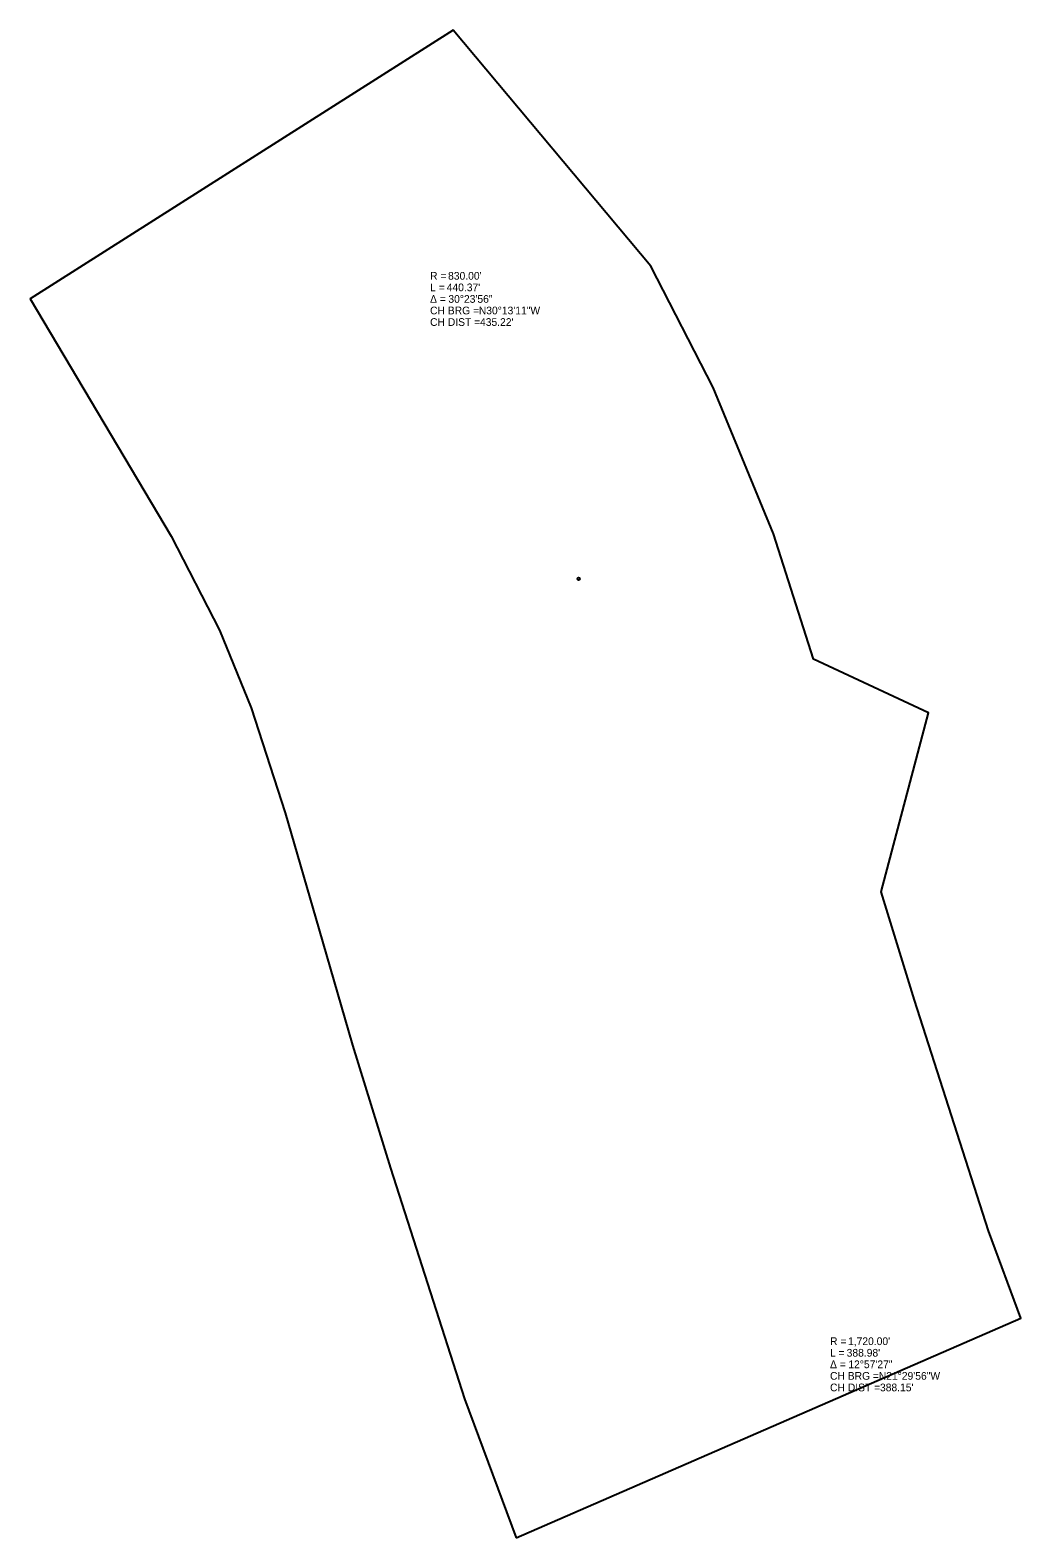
# Model space of a CAD drawing. Extents: x 2392654 to 2393014, y 185039 to 185587.
import ezdxf

# ---------------------------------------------------------------- set-up
doc = ezdxf.new("R2010")
doc.units = 0
for name, color, linetype in [('SV_X_Random_Point', 7, 'Continuous'), ('SV_X_Shot_Marker', 7, 'Continuous'), ('UT_X_Telecom_Cells', 7, 'Continuous')]:
    doc.layers.add(name, color=color, linetype=linetype)

msp = doc.modelspace()

# ---------------------------------------------------------------- linework, layer by layer
at = {"layer": 'SV_X_Random_Point'}
msp.add_circle((2392853.4, 185387.09), 0.5, dxfattribs=at)
at = {"layer": 'SV_X_Shot_Marker'}
msp.add_lwpolyline([(2392830.7, 185038.53), (2393014.09, 185118.34), (2393002.31, 185150.16), (2392988.87, 185192.06), (2392975.44, 185233.96), (2392963.3, 185273.37), (2392980.56, 185338.39), (2392938.75, 185357.88), (2392924.19, 185403.48), (2392902.31, 185456.69), (2392879.63, 185500.76), (2392807.78, 185586.54), (2392654.08, 185488.91), (2392705.35, 185402.64), (2392722.83, 185368.44), (2392734.44, 185340.28), (2392746.69, 185302.09), (2392758.97, 185259.84), (2392771.24, 185217.58), (2392784.99, 185172.89), (2392798.43, 185130.99), (2392811.86, 185089.09)], close=True, dxfattribs=at)

# ---------------------------------------------------------------- texts
at = {"layer": 'UT_X_Telecom_Cells'}
for s, p in [('R = ', (2392799.41, 185495.85)), ("830.00'", (2392805.95, 185495.85)), ('L = ', (2392799.41, 185491.65)), ("440.37'", (2392805.45, 185491.65)), ('Δ = ', (2392799.41, 185487.45)), ('30°23\'56"', (2392806.06, 185487.45)), ('CH BRG = ', (2392799.41, 185483.25)), ('CH DIST = ', (2392799.41, 185479.05)), ('N30°13\'11"W', (2392817.12, 185483.25)), ("435.22'", (2392817.55, 185479.05)), ('R = ', (2392944.75, 185108.6)), ("1,720.00'", (2392951.29, 185108.6)), ('L = ', (2392944.75, 185104.4)), ("388.98'", (2392950.79, 185104.4)), ('Δ = ', (2392944.75, 185100.2)), ('CH BRG = ', (2392944.75, 185096)), ('12°57\'27"', (2392951.4, 185100.2)), ('N21°29\'56"W', (2392962.47, 185096)), ('CH DIST = ', (2392944.75, 185091.8)), ("388.15'", (2392962.9, 185091.8))]:
    msp.add_text(s, height=2.8, dxfattribs=at).set_placement(p)

doc.saveas('drawing.dxf')
